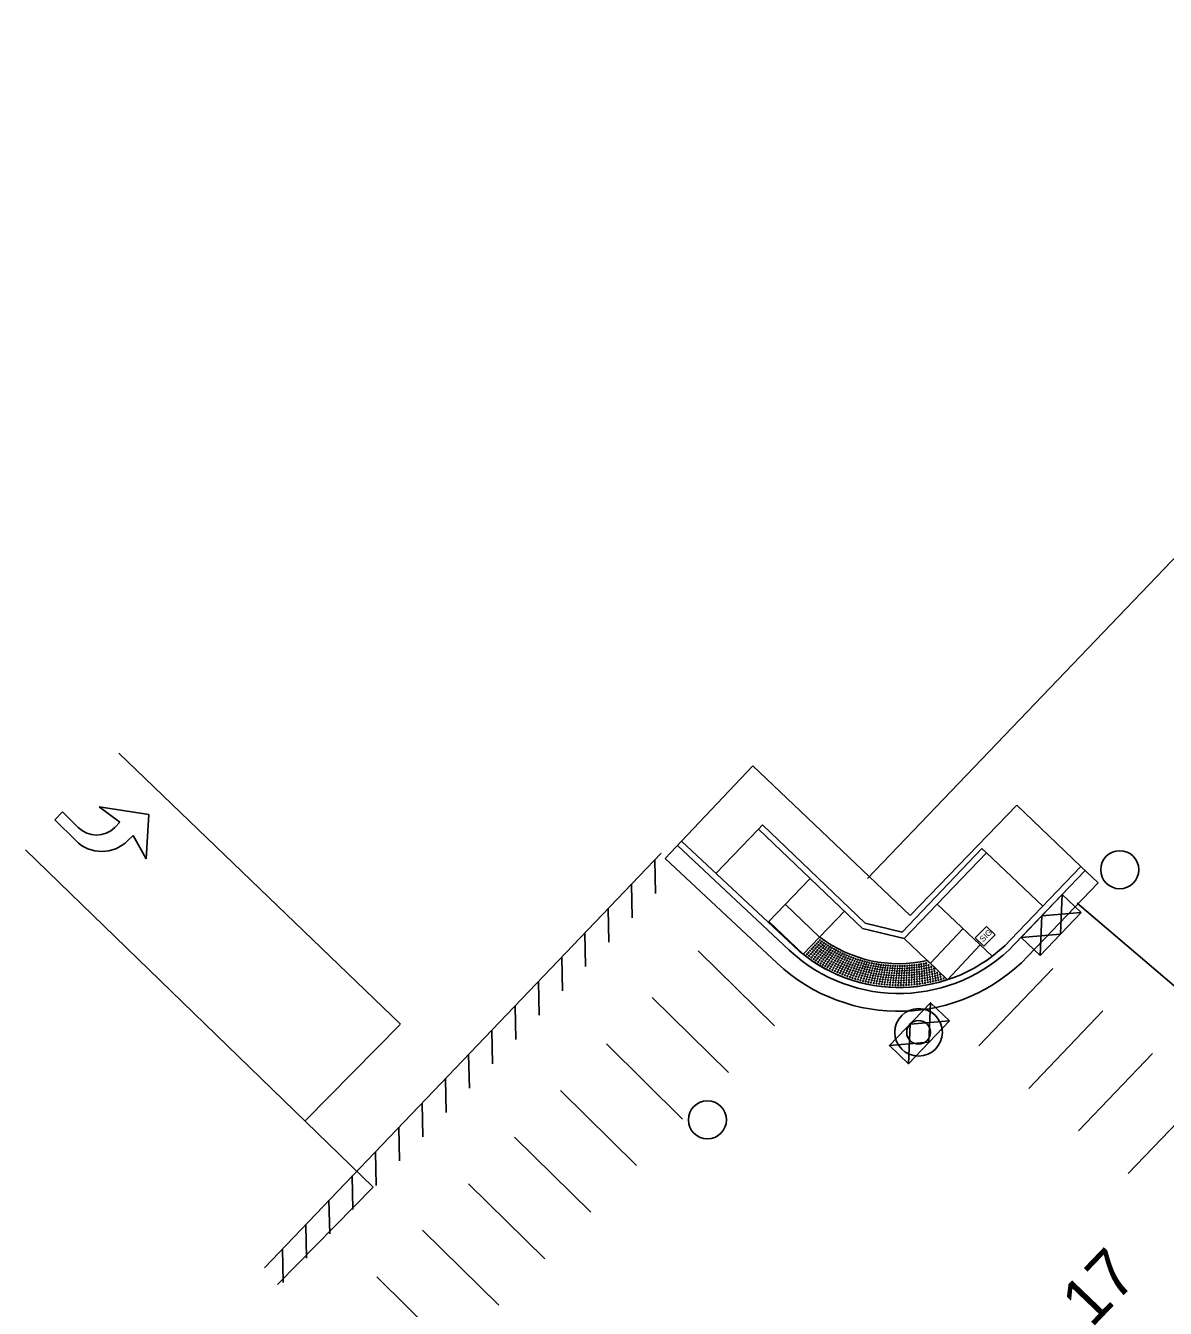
# Model space of a CAD drawing. Extents: x 2377903 to 2496516, y 664638 to 732785.
# Drawn here: x 2378299.8 to 2378395.6, y 730603.2 to 730711.1 of the extents above; entities that cross this region are included whole.
import ezdxf

# ---------------------------------------------------------------- set-up
doc = ezdxf.new("R2010")
doc.units = 0
for name, color, linetype in [('ALG_CL_BLUE_Horiz-Stationing', 7, 'Continuous'), ('Default', 7, 'Continuous'), ('DES_ROADWAY_Curb-Back', 7, 'Continuous'), ('DES_ROADWAY_Curb-Face-LINE STYLE', 7, 'Continuous'), ('DES_ROADWAY_Edge-of-Pavement', 7, 'Continuous'), ('DES_ROADWAY_Misc-SAW CUT', 7, 'Continuous'), ('DES_ROADWAY_Sidewalk', 7, 'Continuous'), ('DES_ROADWAY_T-DOMES', 7, 'Continuous'), ('ENV_EROSN_Temp-Erosn-Ctrl-Details', 7, 'Continuous'), ('ROW_P_PUA', 7, 'Continuous'), ('TOPO_WTRUTIL_Valve', 7, 'Continuous'), ('TRAF_PAVEMARK_Arrows', 7, 'Continuous'), ('TRAF_PAVEMARK_Stop-Bar', 7, 'Continuous'), ('TRAF_PAVEMARK_White_8-IN', 7, 'Continuous'), ('TRAF_PAVEMARK_Yellow-DBL YELLOW', 7, 'Continuous'), ('TRAF_SIGNAL_Composite-Junction-Box', 7, 'Continuous'), ('UTIL_STORM_Manhole', 7, 'Continuous')]:
    doc.layers.add(name, color=color, linetype=linetype)

# ---------------------------------------------------------------- blocks, each defined once
blk = doc.blocks.new('JCTBOX_5')
at = {"layer": 'Default'}
for p, q in [((-0.0086, 0.0064), (0.0086, 0.0064)), ((-0.0086, 0.0064), (-0.0086, -0.0064)), ((0.0086, 0.0064), (0.0086, -0.0064)), ((-0.0086, -0.0064), (0.0086, -0.0064))]:
    blk.add_line(p, q, dxfattribs=at)
blk.add_text('SIG', height=0.00635, dxfattribs=at).set_placement((-0.0063, -0.0031))
blk = doc.blocks.new('MH_7')
at = {"layer": 'Default'}
for radius in [0.0254, 0.0127]:
    blk.add_circle((0, 0), radius, dxfattribs=at)

msp = doc.modelspace()

# ---------------------------------------------------------------- linework, layer by layer
at = {"layer": 'DES_ROADWAY_Curb-Back'}
for p, q in [((2378354.96, 730642.49), (2378364.36, 730633.69)), ((2378382.63, 730634.2), (2378388.54, 730640.37))]:
    msp.add_line(p, q, dxfattribs=at)
msp.add_arc((2378373.24, 730643.18), 13, 226.9025, 316.2619, dxfattribs=at)
at = {"layer": 'DES_ROADWAY_Curb-Face-LINE STYLE'}
for p, q in [((2378354.61, 730642.12), (2378364.02, 730633.33)), ((2378382.99, 730633.85), (2378388.9, 730640.03))]:
    msp.add_line(p, q, dxfattribs=at)
msp.add_arc((2378373.24, 730643.18), 13.5, 226.9025, 316.2619, dxfattribs=at)
at = {"layer": 'DES_ROADWAY_Edge-of-Pavement'}
for p, q in [((2378354.96, 730642.49), (2378353.58, 730641.04)), ((2378319.87, 730606.61), (2378353.24, 730641.47)), ((2378353.58, 730641.04), (2378362.99, 730632.23)), ((2378389.99, 730638.99), (2378388.54, 730640.37)), ((2378384.08, 730632.81), (2378389.99, 730638.99))]:
    msp.add_line(p, q, dxfattribs=at)
msp.add_arc((2378373.24, 730643.18), 15, 226.9025, 316.2619, dxfattribs=at)
at = {"layer": 'DES_ROADWAY_Misc-SAW CUT'}
for p, q in [((2378352.77, 730638.08), (2378352.71, 730640.91)), ((2378350.81, 730636.04), (2378350.75, 730638.87)), ((2378348.85, 730633.99), (2378348.79, 730636.82)), ((2378346.89, 730631.95), (2378346.83, 730634.78)), ((2378344.94, 730629.9), (2378344.88, 730632.73)), ((2378342.98, 730627.86), (2378342.92, 730630.69)), ((2378341.02, 730625.81), (2378340.96, 730628.64)), ((2378339.06, 730623.77), (2378339, 730626.6)), ((2378337.11, 730621.72), (2378337.05, 730624.55)), ((2378335.15, 730619.68), (2378335.09, 730622.51)), ((2378333.19, 730617.63), (2378333.13, 730620.46)), ((2378331.23, 730615.59), (2378331.18, 730618.42)), ((2378329.28, 730613.54), (2378329.22, 730616.37)), ((2378327.32, 730611.5), (2378327.26, 730614.33)), ((2378325.36, 730609.45), (2378325.3, 730612.28)), ((2378323.41, 730607.41), (2378323.35, 730610.24)), ((2378321.45, 730605.36), (2378321.39, 730608.19))]:
    msp.add_line(p, q, dxfattribs=at)
at = {"layer": 'DES_ROADWAY_Sidewalk'}
for p, q in [((2378360.94, 730648.83), (2378354.96, 730642.49)), ((2378374.17, 730636.24), (2378360.94, 730648.83)), ((2378383.16, 730645.53), (2378374.17, 730636.24)), ((2378383.16, 730645.53), (2378388.54, 730640.37)), ((2378357.85, 730639.78), (2378361.42, 730643.5)), ((2378361.77, 730643.87), (2378361.42, 730643.5)), ((2378361.42, 730643.5), (2378370.16, 730635.14)), ((2378361.77, 730643.87), (2378370.41, 730635.59)), ((2378373.51, 730634.85), (2378380.22, 730641.86)), ((2378373.67, 730634.29), (2378380.59, 730641.52)), ((2378380.22, 730641.86), (2378380.59, 730641.52)), ((2378380.59, 730641.52), (2378385.35, 730637.03)), ((2378362.24, 730635.68), (2378365.76, 730639.36)), ((2378363.68, 730637.19), (2378366.57, 730634.42)), ((2378365.19, 730632.98), (2378368.65, 730636.59)), ((2378376.44, 730637.18), (2378381.08, 730632.81)), ((2378362.3, 730635.74), (2378365.19, 730632.98)), ((2378370.41, 730635.59), (2378373.51, 730634.85)), ((2378370.16, 730635.14), (2378373.67, 730634.29)), ((2378378.62, 730635.13), (2378375.88, 730632.22)), ((2378373.67, 730634.29), (2378377.33, 730630.84)), ((2378380.08, 730633.76), (2378377.33, 730630.84))]:
    msp.add_line(p, q, dxfattribs=at)
at = {"layer": 'DES_ROADWAY_T-DOMES'}
for p, q in [((2378365.19, 730632.98), (2378366.58, 730634.43)), ((2378375.63, 730632.45), (2378377.33, 730630.84))]:
    msp.add_line(p, q, dxfattribs=at)
for centre in [(2378365.92, 730633.43), (2378366.05, 730633.57), (2378366.19, 730633.72), (2378366.23, 730633.45), (2378366.33, 730633.87), (2378366.36, 730633.6), (2378366.4, 730633.32), (2378366.46, 730634.02), (2378366.49, 730633.75), (2378366.53, 730633.48), (2378366.6, 730634.16), (2378366.63, 730633.9), (2378366.66, 730633.63), (2378366.71, 730633.36), (2378366.76, 730634.05), (2378366.8, 730633.78), (2378366.84, 730633.51), (2378366.93, 730633.93), (2378366.96, 730633.67), (2378367.01, 730633.4), (2378367.09, 730633.82), (2378367.13, 730633.56), (2378367.26, 730633.71), (2378367.31, 730633.45), (2378367.43, 730633.61), (2378367.48, 730633.34), (2378367.6, 730633.51), (2378367.78, 730633.41), (2378365.51, 730632.98), (2378365.64, 730633.13), (2378365.69, 730632.85), (2378365.78, 730633.28), (2378365.83, 730633), (2378365.88, 730632.71), (2378365.96, 730633.15), (2378366.01, 730632.87), (2378366.07, 730632.58), (2378366.09, 730633.3), (2378366.14, 730633.02), (2378366.19, 730632.74), (2378366.26, 730632.46), (2378366.27, 730633.17), (2378366.32, 730632.89), (2378366.38, 730632.61), (2378366.45, 730633.05), (2378366.45, 730632.33), (2378366.51, 730632.77), (2378366.57, 730632.49), (2378366.58, 730633.2), (2378366.63, 730632.93), (2378366.69, 730632.65), (2378366.76, 730633.09), (2378366.76, 730632.38), (2378366.82, 730632.81), (2378366.88, 730633.24), (2378366.88, 730632.54), (2378366.94, 730632.97), (2378366.96, 730632.26), (2378367, 730632.7), (2378367.06, 730633.13), (2378367.07, 730632.43), (2378367.12, 730632.86), (2378367.19, 730633.29), (2378367.19, 730632.59), (2378367.24, 730633.02), (2378367.27, 730632.32), (2378367.31, 730632.75), (2378367.36, 730633.18), (2378367.38, 730632.48), (2378367.43, 730632.92), (2378367.5, 730632.65), (2378367.54, 730633.08), (2378367.57, 730632.38), (2378367.61, 730632.81), (2378367.66, 730633.24), (2378367.68, 730632.55), (2378367.72, 730632.98), (2378367.77, 730632.28), (2378367.8, 730632.72), (2378367.84, 730633.15), (2378367.88, 730632.45), (2378367.91, 730632.88), (2378367.95, 730633.31), (2378367.98, 730632.62), (2378368.02, 730633.05), (2378368.07, 730632.36), (2378368.09, 730632.79), (2378368.13, 730633.22), (2378368.17, 730632.53), (2378368.2, 730632.96), (2378368.26, 730632.27), (2378368.28, 730632.7), (2378368.31, 730633.13), (2378368.36, 730632.44), (2378368.38, 730632.87), (2378368.47, 730632.61), (2378368.49, 730633.04), (2378368.56, 730632.35), (2378368.57, 730632.79), (2378368.66, 730632.53), (2378368.67, 730632.96), (2378368.75, 730632.27), (2378368.75, 730632.7), (2378368.85, 730632.45), (2378368.85, 730632.88), (2378368.94, 730632.63), (2378369.04, 730632.8), (2378369.04, 730632.37), (2378369.13, 730632.55), (2378369.22, 730632.73), (2378369.23, 730632.3), (2378369.32, 730632.48), (2378369.41, 730632.66), (2378369.51, 730632.41), (2378369.6, 730632.59), (2378369.71, 730632.35), (2378369.79, 730632.53), (2378369.9, 730632.28), (2378369.98, 730632.47), (2378370.17, 730632.41), (2378370.36, 730632.36), (2378370.56, 730632.31), (2378370.75, 730632.26), (2378366.64, 730632.21), (2378366.84, 730632.1), (2378367.04, 730631.99), (2378367.15, 730632.15), (2378367.24, 730631.88), (2378367.35, 730632.04), (2378367.44, 730631.77), (2378367.46, 730632.21), (2378367.55, 730631.94), (2378367.65, 730631.67), (2378367.66, 730632.11), (2378367.75, 730631.84), (2378367.86, 730632.01), (2378367.85, 730631.57), (2378367.96, 730631.75), (2378367.96, 730632.18), (2378368.06, 730631.92), (2378368.06, 730631.48), (2378368.16, 730632.09), (2378368.16, 730631.65), (2378368.26, 730631.83), (2378368.27, 730631.39), (2378368.36, 730632), (2378368.37, 730631.56), (2378368.46, 730632.18), (2378368.46, 730631.74), (2378368.48, 730631.3), (2378368.56, 730631.92), (2378368.58, 730631.48), (2378368.66, 730632.09), (2378368.67, 730631.66), (2378368.7, 730631.22), (2378368.76, 730631.84), (2378368.79, 730631.4), (2378368.85, 730632.01), (2378368.88, 730631.58), (2378368.95, 730632.19), (2378368.96, 730631.76), (2378369, 730631.32), (2378369.05, 730631.94), (2378369.08, 730631.5), (2378369.14, 730632.12), (2378369.17, 730631.68), (2378369.21, 730631.25), (2378369.26, 730631.86), (2378369.29, 730631.43), (2378369.34, 730632.05), (2378369.38, 730631.61), (2378369.43, 730632.23), (2378369.42, 730631.18), (2378369.46, 730631.8), (2378369.5, 730631.36), (2378369.54, 730631.98), (2378369.58, 730631.54), (2378369.62, 730632.16), (2378369.66, 730631.73), (2378369.71, 730631.3), (2378369.74, 730631.91), (2378369.79, 730631.48), (2378369.82, 730632.1), (2378369.87, 730631.67), (2378369.93, 730631.23), (2378369.94, 730631.85), (2378370, 730631.42), (2378370.02, 730632.04), (2378370.07, 730631.61), (2378370.1, 730632.23), (2378370.14, 730631.18), (2378370.15, 730631.8), (2378370.21, 730631.37), (2378370.22, 730631.98), (2378370.28, 730631.55), (2378370.29, 730632.17), (2378370.35, 730631.74), (2378370.42, 730631.93), (2378370.42, 730631.31), (2378370.49, 730632.12), (2378370.49, 730631.5), (2378370.55, 730631.69), (2378370.62, 730631.88), (2378370.63, 730631.26), (2378370.69, 730632.07), (2378370.7, 730631.46), (2378370.76, 730631.65), (2378370.82, 730631.84), (2378370.85, 730631.22), (2378370.89, 730632.03), (2378370.91, 730631.41), (2378370.95, 730632.22), (2378370.97, 730631.6), (2378371.03, 730631.8), (2378371.06, 730631.18), (2378371.09, 730631.99), (2378371.12, 730631.37), (2378371.14, 730632.18), (2378371.17, 730631.57), (2378371.23, 730631.76), (2378371.29, 730631.95), (2378371.33, 730631.34), (2378371.34, 730632.15), (2378371.38, 730631.53), (2378371.43, 730631.72), (2378371.49, 730631.92), (2378371.54, 730632.11), (2378371.54, 730631.3), (2378371.59, 730631.5), (2378371.64, 730631.69), (2378371.69, 730631.89), (2378371.74, 730632.08), (2378371.75, 730631.28), (2378371.8, 730631.47), (2378371.84, 730631.67), (2378371.89, 730631.86), (2378371.94, 730632.06), (2378371.97, 730631.25), (2378372.01, 730631.45), (2378372.05, 730631.64), (2378372.09, 730631.84), (2378372.13, 730632.04), (2378372.18, 730631.23), (2378372.22, 730631.43), (2378372.26, 730631.63), (2378372.29, 730631.82), (2378372.33, 730632.02), (2378372.39, 730631.21), (2378372.43, 730631.41), (2378372.46, 730631.61), (2378372.5, 730631.81), (2378372.53, 730632.01), (2378372.61, 730631.2), (2378372.64, 730631.4), (2378372.67, 730631.6), (2378372.7, 730631.8), (2378372.73, 730631.99), (2378372.82, 730631.19), (2378372.85, 730631.39), (2378372.88, 730631.59), (2378372.9, 730631.79), (2378372.93, 730631.99), (2378373.04, 730631.19), (2378373.06, 730631.38), (2378373.08, 730631.58), (2378373.11, 730631.78), (2378373.13, 730631.98), (2378373.25, 730631.18), (2378373.27, 730631.38), (2378373.29, 730631.58), (2378373.31, 730631.78), (2378373.33, 730631.98), (2378373.46, 730631.19), (2378373.48, 730631.39), (2378373.5, 730631.59), (2378373.52, 730631.79), (2378373.53, 730631.99), (2378373.68, 730631.19), (2378373.69, 730631.39), (2378373.71, 730631.59), (2378373.72, 730631.79), (2378373.73, 730631.99), (2378373.89, 730631.2), (2378373.9, 730631.4), (2378373.91, 730631.6), (2378373.92, 730631.8), (2378373.93, 730632), (2378374.11, 730631.42), (2378374.11, 730631.21), (2378374.12, 730631.62), (2378374.13, 730632.02), (2378374.12, 730631.82), (2378374.32, 730631.43), (2378374.32, 730631.23), (2378374.33, 730632.04), (2378374.33, 730631.84), (2378374.33, 730631.63), (2378374.53, 730632.06), (2378374.53, 730631.86), (2378374.53, 730631.66), (2378374.53, 730631.45), (2378374.53, 730631.25), (2378374.73, 730632.08), (2378374.73, 730631.88), (2378374.74, 730631.68), (2378374.74, 730631.48), (2378374.75, 730631.28), (2378374.93, 730632.11), (2378374.93, 730631.91), (2378374.94, 730631.71), (2378374.95, 730631.51), (2378374.96, 730631.31), (2378375.12, 730632.14), (2378375.13, 730631.94), (2378375.15, 730631.74), (2378375.16, 730631.54), (2378375.17, 730631.34), (2378375.32, 730632.18), (2378375.34, 730631.98), (2378375.35, 730631.78), (2378375.37, 730631.58), (2378375.38, 730631.38), (2378375.4, 730631.18), (2378375.52, 730632.22), (2378375.54, 730632.02), (2378375.55, 730631.82), (2378375.57, 730631.62), (2378375.59, 730631.42), (2378375.61, 730631.22), (2378375.73, 730632.06), (2378375.76, 730631.86), (2378375.78, 730631.66), (2378375.8, 730631.46), (2378375.82, 730631.26), (2378375.96, 730631.91), (2378375.98, 730631.71), (2378376.01, 730631.51), (2378376.04, 730631.31), (2378376.19, 730631.76), (2378376.22, 730631.56), (2378376.25, 730631.36), (2378376.28, 730631.16), (2378376.46, 730631.42), (2378376.49, 730631.22), (2378376.7, 730631.28), (2378368.91, 730631.14), (2378369.13, 730631.06), (2378369.34, 730630.99), (2378369.56, 730630.92), (2378369.64, 730631.11), (2378369.78, 730630.86), (2378369.85, 730631.05), (2378370, 730630.8), (2378370.07, 730630.99), (2378370.22, 730630.74), (2378370.29, 730630.93), (2378370.36, 730631.12), (2378370.45, 730630.69), (2378370.51, 730630.88), (2378370.57, 730631.07), (2378370.67, 730630.64), (2378370.73, 730630.84), (2378370.79, 730631.03), (2378370.89, 730630.6), (2378370.95, 730630.79), (2378371.01, 730630.99), (2378371.12, 730630.56), (2378371.17, 730630.75), (2378371.22, 730630.95), (2378371.28, 730631.14), (2378371.35, 730630.52), (2378371.39, 730630.72), (2378371.44, 730630.91), (2378371.49, 730631.11), (2378371.57, 730630.49), (2378371.62, 730630.69), (2378371.66, 730630.88), (2378371.71, 730631.08), (2378371.8, 730630.46), (2378371.84, 730630.66), (2378371.88, 730630.86), (2378371.92, 730631.05), (2378372.03, 730630.44), (2378372.06, 730630.64), (2378372.1, 730630.84), (2378372.14, 730631.03), (2378372.25, 730630.42), (2378372.29, 730630.62), (2378372.32, 730630.82), (2378372.36, 730631.02), (2378372.48, 730630.41), (2378372.51, 730630.6), (2378372.54, 730630.8), (2378372.58, 730631), (2378372.71, 730630.39), (2378372.74, 730630.59), (2378372.77, 730630.79), (2378372.79, 730630.99), (2378372.94, 730630.39), (2378372.96, 730630.59), (2378372.99, 730630.79), (2378373.01, 730630.99), (2378373.17, 730630.38), (2378373.19, 730630.58), (2378373.21, 730630.78), (2378373.23, 730630.98), (2378373.4, 730630.38), (2378373.41, 730630.58), (2378373.43, 730630.78), (2378373.45, 730630.99), (2378373.62, 730630.39), (2378373.64, 730630.59), (2378373.65, 730630.79), (2378373.66, 730630.99), (2378373.86, 730630.6), (2378373.85, 730630.4), (2378373.87, 730630.8), (2378373.88, 730631), (2378374.08, 730630.41), (2378374.09, 730630.61), (2378374.1, 730631.01), (2378374.09, 730630.81), (2378374.31, 730630.63), (2378374.31, 730630.43), (2378374.32, 730631.03), (2378374.31, 730630.83), (2378374.53, 730631.05), (2378374.53, 730630.85), (2378374.54, 730630.65), (2378374.54, 730630.45), (2378374.75, 730631.08), (2378374.75, 730630.88), (2378374.76, 730630.68), (2378374.76, 730630.47), (2378374.97, 730631.11), (2378374.97, 730630.91), (2378374.98, 730630.7), (2378374.99, 730630.5), (2378375.18, 730631.14), (2378375.19, 730630.94), (2378375.2, 730630.74), (2378375.22, 730630.54), (2378375.41, 730630.97), (2378375.43, 730630.77), (2378375.44, 730630.57), (2378375.63, 730631.02), (2378375.65, 730630.82), (2378375.67, 730630.62), (2378375.85, 730631.06), (2378375.87, 730630.86), (2378375.89, 730630.66), (2378376.06, 730631.11), (2378376.09, 730630.91), (2378376.11, 730630.71), (2378376.31, 730630.96), (2378376.34, 730630.76), (2378376.52, 730631.02), (2378376.56, 730630.82), (2378376.74, 730631.08), (2378376.78, 730630.88), (2378377, 730630.95)]:
    msp.add_circle(centre, 0.0375, dxfattribs=at)
for radius, start, end in [(11, 232.7266, 282.5543), (13, 231.727, 288.3462)]:
    msp.add_arc((2378373.24, 730643.18), radius, start, end, dxfattribs=at)
at = {"layer": 'ENV_EROSN_Temp-Erosn-Ctrl-Details'}
for points in [[(2378388.57, 730636.49), (2378385.11, 730632.88), (2378383.52, 730634.4), (2378386.98, 730638.01)], [(2378377.49, 730627.38), (2378374.03, 730623.77), (2378372.44, 730625.29), (2378375.9, 730628.9)]]:
    msp.add_lwpolyline(points, close=True, dxfattribs=at)
for points in [[(2378386.98, 730638.01), (2378386.84, 730634.68), (2378383.52, 730634.4)], [(2378385.11, 730632.88), (2378385.25, 730636.21), (2378388.57, 730636.49)], [(2378375.9, 730628.9), (2378375.76, 730625.57), (2378372.44, 730625.29)], [(2378374.03, 730623.77), (2378374.17, 730627.1), (2378377.49, 730627.38)]]:
    msp.add_lwpolyline(points, dxfattribs=at)
at = {"layer": 'ROW_P_PUA'}
msp.add_line((2378370.59, 730639.35), (2378439.26, 730711.09), dxfattribs=at)
at = {"layer": 'TOPO_WTRUTIL_Valve'}
for centre in [(2378391.81, 730640.09), (2378357.13, 730619.05)]:
    msp.add_circle(centre, 1.6, dxfattribs=at)
at = {"layer": 'TRAF_PAVEMARK_Arrows'}
for p, q in [((2378310.14, 730644.74), (2378305.97, 730645.39)), ((2378305.97, 730645.39), (2378307.72, 730644.08)), ((2378302.89, 730644.95), (2378302.24, 730644.29)), ((2378302.24, 730644.29), (2378304, 730642.54)), ((2378304.21, 730643.63), (2378302.89, 730644.95)), ((2378309.92, 730641.01), (2378310.14, 730644.74)), ((2378307.72, 730644.08), (2378307.29, 730643.64)), ((2378308.39, 730642.54), (2378308.82, 730642.98)), ((2378308.82, 730642.98), (2378309.92, 730641.01))]:
    msp.add_line(p, q, dxfattribs=at)
for centre, radius in [((2378305.75, 730645.17), 2.17), ((2378306.19, 730644.73), 3.1)]:
    msp.add_arc(centre, radius, 225.1092, 315.1092, dxfattribs=at)
at = {"layer": 'TRAF_PAVEMARK_Stop-Bar'}
for p, q in [((2378406.76, 730621.46), (2378388.24, 730637.27)), ((2378362.76, 730626.95), (2378356.35, 730633.27)), ((2378379.96, 730625.28), (2378386.19, 730631.79)), ((2378358.9, 730623.03), (2378352.49, 730629.35)), ((2378384.15, 730621.7), (2378390.38, 730628.21)), ((2378331.29, 730627.07), (2378323.29, 730618.96)), ((2378355.04, 730619.11), (2378348.63, 730625.43)), ((2378388.34, 730618.12), (2378394.57, 730624.63)), ((2378351.18, 730615.2), (2378344.77, 730621.52)), ((2378392.53, 730614.54), (2378398.76, 730621.05)), ((2378347.32, 730611.28), (2378340.91, 730617.6)), ((2378329.03, 730613.38), (2378320.96, 730605.19)), ((2378343.45, 730607.36), (2378337.04, 730613.68)), ((2378339.59, 730603.45), (2378333.18, 730609.76)), ((2378335.73, 730599.53), (2378329.32, 730605.85))]:
    msp.add_line(p, q, dxfattribs=at)
at = {"layer": 'TRAF_PAVEMARK_White_8-IN'}
msp.add_line((2378299.79, 730641.76), (2378329.03, 730613.38), dxfattribs=at)
at = {"layer": 'TRAF_PAVEMARK_Yellow-DBL YELLOW'}
msp.add_line((2378307.64, 730649.9), (2378331.31, 730627.09), dxfattribs=at)

# ---------------------------------------------------------------- block references
at = {"layer": 'TRAF_SIGNAL_Composite-Junction-Box', "xscale": 78.74000000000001, "yscale": 78.74, "rotation": 45.14948012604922}
msp.add_blockref('JCTBOX_5', (2378380.49, 730634.49), dxfattribs=at)
at = {"layer": 'UTIL_STORM_Manhole', "xscale": 78.74000000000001, "yscale": 78.74000000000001}
msp.add_blockref('MH_7', (2378374.89, 730626.41), dxfattribs=at)

# ---------------------------------------------------------------- texts
at = {"layer": 'ALG_CL_BLUE_Horiz-Stationing'}
msp.add_text('17', height=4, rotation=46.2512, dxfattribs=at).set_placement((2378389.43, 730601.47))

doc.saveas('drawing.dxf')
